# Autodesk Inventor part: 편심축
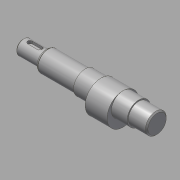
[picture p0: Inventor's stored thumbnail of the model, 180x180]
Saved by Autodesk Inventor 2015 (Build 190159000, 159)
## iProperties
Created: 2017-08
Part Number: 편심축
Material: 강철, 연강
Document SubType Name: Modeling
Designer: mduedu
Density: 7.86 g/cm^3
Appearance: 강철
Mass: 231.594 g
Surface Area: 73.7561 cm^2
Volume: 29.4649 cm^3
Author: mduedu
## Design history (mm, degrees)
sketch "스케치1"
  geometry: L1 (0, 0)-(110, 0); L2 (110, 0)-(110, 8.5); L3 (110, 8.5)-(95, 8.5); L4 (95, 8.5)-(95, 9.5); L5 (95, 9.5)-(51, 9.5); L6 (51, 9.5)-(51, 8.5); L7 (51, 8.5)-(19, 8.5); L8 (19, 8.5)-(19, 6); L9 (19, 6)-(0, 6); L10 (0, 6)-(0, 0)
  constraints: 20 end point, 6 parallel, 2 collinear, 2 perpendicular, 1 horizontal
  dimensions: "d0" = 110 distance of L1.start L1.end; "d1" = 17 diameter of L3 L1; "d2" = 19 diameter of L5 L1; "d3" = 12 diameter of L9 L1; "d4" = 19 distance of L8.end L9.end; "d5" = 15 distance of L2.end L3.end; "d6" = 44 distance of L4.end L5.end
revolve "회전1" sketch "스케치1" stored, may be unused: angle "d7" = 90 deg
node "작업 평면1"
sketch "스케치2"
  geometry: C1 r 9.5 at (0, 0) reference; C2 r 13 at (0, -3.5); 1 further point
  constraints: 1 centre point, 1 tangent, 1 vertical alignment
  dimensions: "d8" = 3.5 distance of point (0, 0) C2.centre
extrude "돌출1" join sketch "스케치2" stored distance "d9" = 18; taper "d10" = 0 deg
chamfer "모따기1" distance "d11" = 1; stored, may be unused: second distance "d12" = 2, angle "d13" = 45 deg
node "작업 평면2"
sketch "스케치3"
  geometry: L1 (3.5, -2)-(-4.5, -2); L2 (-4.5, -2)-(-4.5, 2); L3 (-4.5, 2)-(3.5, 2); L4 (3.5, 2)-(3.5, -2); L5 (9.5, 6)-(9.5, -6) reference; A1 r 2 centre (3.5, 0) between (3.5, -2) and (3.5, 2); A2 r 2 centre (-4.5, 0) between (-4.5, 2) and (-4.5, -2); A3 r 2 centre (3.5, 0) between (3.5, 2) and (3.5, -2); A4 r 2 centre (-4.5, 0) between (-4.5, -2) and (-4.5, 2); 1 further point
  constraints: 8 end point, 8 point on circle, 4 centre point, 2 midpoint, 2 parallel, 1 horizontal, 1 horizontal alignment, 1 perpendicular
  dimensions: "d14" = 12 dimension on A2 A1; "d16" = 4 distance between parallel lines of L3 L1; "d17" = 4 distance edge to line of A1 L5
extrude "돌출2" cut sketch "스케치3" distance "d18" = 2.5; taper "d19" = 0 deg
chamfer "모따기2" distance "d20" = 1; stored, may be unused: second distance "d21" = 2, angle "d22" = 45 deg
chamfer "모따기3" distance "d23" = 1; stored, may be unused: second distance "d24" = 2, angle "d25" = 60 deg
fillet "모깎기1" dims "d26" = 0.5
hole "구멍1" diameter "d29" = 3.242; stored, may be unused: countersink angle "d33" = 90 deg, drill point angle "d35" = 118 deg; dims "d30" = 8, "d31" = 4, "d32" = 2, "d34" = 10, "d36" = 10, "d37" = 10
node "솔리드1"
node "절단 모서리 투영1"
